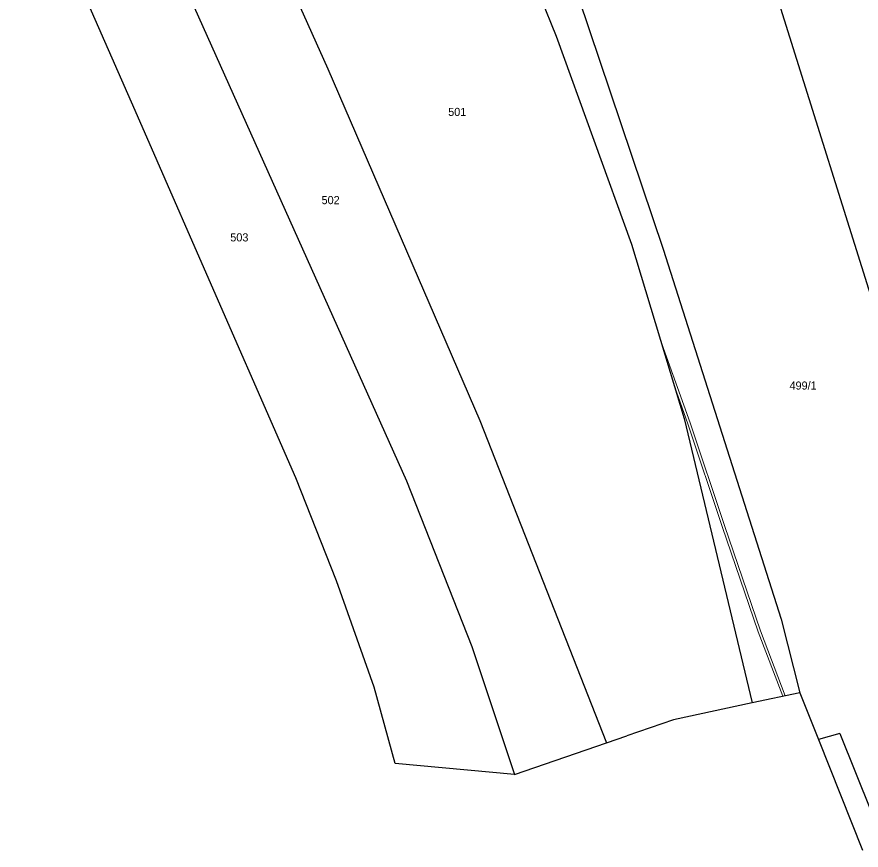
# Model space of a CAD drawing. Extents: x -664548 to -662415, y -1069720 to -1068208.
# Drawn here: x -664401.9 to -664224.9, y -1069516.2 to -1069341.5 of the extents above; entities that cross this region are included whole.
import ezdxf

# ---------------------------------------------------------------- set-up
doc = ezdxf.new("R2010")
doc.units = 0
doc.header["$LTSCALE"] = 0.68
doc.layers.add('1', color=7, linetype='Continuous', lineweight=25)
doc.layers.add('13', color=7, linetype='Continuous', lineweight=13)
doc.layers.add('2', color=7, linetype='Continuous')

msp = doc.modelspace()

# ---------------------------------------------------------------- linework, layer by layer
at = {"layer": '1'}
for p, q in [((-664382.72, -1069249.61), (-664336.71, -1069352.37)), ((-664401.91, -1069256.47), (-664320.21, -1069438.74)), ((-664304.43, -1069306.57), (-664288.82, -1069345.56)), ((-664247.65, -1069321.07), (-664192.8, -1069496)), ((-664377.89, -1069359.38), (-664391.2, -1069328.98)), ((-664284.13, -1069337.46), (-664266.42, -1069390.2)), ((-664288.82, -1069345.56), (-664273.02, -1069389.18)), ((-664336.71, -1069352.37), (-664304.82, -1069426.11)), ((-664374.17, -1069367.87), (-664377.89, -1069359.38)), ((-664370.82, -1069375.52), (-664374.17, -1069367.87)), ((-664364.03, -1069391.02), (-664370.82, -1069375.52)), ((-664273.02, -1069389.18), (-664261.96, -1069425.69)), ((-664343.41, -1069438.11), (-664364.03, -1069391.02)), ((-664266.42, -1069390.2), (-664241.66, -1069467.73)), ((-664304.82, -1069426.11), (-664278.26, -1069493.68)), ((-664261.96, -1069425.69), (-664247.75, -1069485.3)), ((-664334.87, -1069459.69), (-664343.41, -1069438.11)), ((-664320.21, -1069438.74), (-664306.49, -1069473.49)), ((-664326.98, -1069481.99), (-664334.87, -1069459.69)), ((-664241.66, -1069467.73), (-664237.75, -1069483.16)), ((-664306.49, -1069473.49), (-664297.55, -1069500.32)), ((-664322.57, -1069497.98), (-664326.98, -1069481.99)), ((-664237.75, -1069483.16), (-664247.75, -1069485.3)), ((-664237.75, -1069483.16), (-664233.83, -1069493)), ((-664247.75, -1069485.3), (-664264.2, -1069488.83)), ((-664264.2, -1069488.83), (-664273.98, -1069492.2)), ((-664278.26, -1069493.68), (-664273.98, -1069492.2)), ((-664229.34, -1069491.74), (-664233.83, -1069493)), ((-664229.34, -1069491.74), (-664222.8, -1069508.08)), ((-664297.55, -1069500.32), (-664278.26, -1069493.68)), ((-664233.83, -1069493), (-664224.61, -1069516.16)), ((-664297.55, -1069500.32), (-664322.57, -1069497.98))]:
    msp.add_line(p, q, dxfattribs=at)
at = {"layer": '13'}
msp.add_lwpolyline([(-664261.21, -1069426.78), (-664254.01, -1069448.3), (-664246.46, -1069470.38), (-664241.29, -1069483.92), (-664240.8, -1069483.81), (-664245.98, -1069470.2), (-664253.53, -1069448.14), (-664260.73, -1069426.62), (-664266.99, -1069409.07), (-664264.01, -1069418.93)], close=True, dxfattribs=at)

# ---------------------------------------------------------------- texts
at = {"layer": '2'}
for s, p in [('501', (-664311.47, -1069362.275)), ('502', (-664338.02, -1069380.765)), ('503', (-664357.16, -1069388.574)), ('499/1', (-664239.9, -1069419.635))]:
    msp.add_text(s, height=1.7, dxfattribs=at).set_placement(p)

doc.saveas('drawing.dxf')
